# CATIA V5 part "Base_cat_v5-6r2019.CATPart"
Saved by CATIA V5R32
Part number: Base
Bounding box of the stored display mesh (mm): x -32 to 32, y 0 to 144, z 0 to 52
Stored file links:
  D:\PROJECTS\Project 2022\CATIA V5 6R 2022\Resources\Tutorial Files\c16_catia_v5_6r2022_tut\Bench vice\Base_cat_v5-6r2019.CATPart
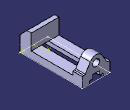
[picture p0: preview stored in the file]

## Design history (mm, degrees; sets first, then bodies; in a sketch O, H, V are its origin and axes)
Body1 (main body)
  Sketch1 on xy-plane, origin (0, 0, 0), H (1, 0, 0), V (0, 1, 0)
    point P1 (-32, 0)
    line L1 (-32, 0) -> (32, 0)
    line L2 (32, 0) -> (32, 144)
    line L3 (32, 144) -> (-32, 144)
    line L4 (-32, 144) -> (-32, 0)
    length L1 = 64
    length L2 = 144
    distance V L2 = 32
    coincidence: P1 H
    horizontal: L1 H, L3 H
    vertical: L2 V, L4 V
  Pad1: profile Sketch1, direction (0, 0, 1), length 16
  Sketch2 on face of Pad1, origin (32, 0, 0), H (0, 1, 0), V (0, 0, 1)
    point P1 (0, 16)
    line L1 (0, 16) -> (0, 36)
    point P2 (0, 36)
    line L2 (26, 52) -> (26, 16)
    line L3 (26, 16) -> (0, 16)
    reference projected line E1 (144, 16) -> (0, 16) from edge of Pad1
    line L4 (26, 52) -> (16, 52)
    point P5 (16, 52)
    line L5 (16, 52) -> (0, 36)
    length L2 = 36
    distance P5 P2 H = 16
    distance P5 P2 V = 16
    length L3 = 26
    coincidence: P1 V, E1 L3
    vertical: L1 V, L2 V
    horizontal: L3 H, L4 H
  Pad2: profile Sketch2, direction (-1, 0, 0), length 64
  Sketch3 on face of Pad1, origin (0, 144, 0), H (-1, 0, 0), V (0, 0, 1)
    line L1 (-32, 16) -> (-32, 24)
    point P2 (32, 24)
    line L2 (32, 24) -> (32, 16)
    line L3 (32, 16) -> (-32, 16)
    reference projected line E1 (32, 16) -> (-32, 16) from edge of Pad1
    line L4 (32, 24) -> (26, 24)
    point P4 (26, 24)
    line L5 (26, 24) -> (13.6777, 44.3018)
    point P5 (0, 52)
    line L6 (-13.6777, 44.3018) -> (-26, 24)
    point P6 (-26, 24)
    line L7 (-26, 24) -> (-32, 24)
    reference projected line E2 (32, 52) -> (-32, 52) from edge of Pad2
    reference projected line E3 (32, 16) -> (32, 52) from edge of Pad2
    reference projected line E4 (-32, 0) -> (-32, 16) from edge of Pad1
    arc A1 centre (0, 36) radius 16 from (13.6777, 44.3018) to (-13.6777, 44.3018) ccw
    point P8 (0, 36)
    reference projected line E5 (32, 52) -> (-32, 52) from edge of Pad2
    circle A2 centre (0, 36) radius 8
    distance H P2 = 24
    distance P6 P4 = 52
    distance P6 V = 26
    radius A1 = 16
    radius A2 = 8
    vertical: L1 V, L2 V
    horizontal: L3 H, L4 H, L7 H
    coincidence: L3 E1, P5 V, P6 L4, P5 E2, L2 E3, L1 E4, P8 V
    tangency: A1 E5, L6 A1, A1 L5
  Pad3: profile Sketch3, direction (0, -1, 0), length 22
  Fillet1: radius 3, on 2 edges
  Sketch4 on face of Pad1, origin (0, 144, 0), H (-1, 0, 0), V (0, 0, 1)
    point P1 (-16, 0)
    line L1 (-16, 0) -> (-16, 7)
    point P2 (-16, 7)
    line L2 (-16, 7) -> (-8, 7)
    point P3 (-8, 7)
    line L3 (-8, 7) -> (-8, 16)
    point P4 (-8, 16)
    line L4 (-8, 16) -> (0, 16)
    point P5 (0, 16)
    point P6 (16, 7)
    point P7 (16, 0)
    line L5 (16, 0) -> (16, 7)
    point P8 (8, 7)
    line L6 (16, 7) -> (8, 7)
    point P9 (8, 16)
    line L7 (8, 7) -> (8, 16)
    point P10 (0, 16)
    line L8 (8, 16) -> (0, 16)
    line L9 (-16, 0) -> (16, 0)
    point P11 (16, 0)
    distance L1 V = 16
    distance L3 V = 8
    distance H L4 = 16
    distance H L2 = 7
    coincidence: P1 H, P5 V, P7 P11, P5 P10
    vertical: L1 V, L3 V
    horizontal: L2 H, L4 H, L9 H
    symmetry: P2 P6 V, P1 P7 V, L1 L5 V, P3 P8 V, L2 L6 V, P4 P9 V, L3 L7 V, P5 P10 V, L4 L8 V
  Pocket1: profile Sketch4, direction (0, -1, 0), through (limit type 3)
  Sketch5 on face of Pad1, origin (0, 0, 0), H (1, 0, 0), V (0, -1, 0)
    circle A1 centre (22, -38) radius 3
    point P1 (22, -38)
    reference projected line E1 (32, 0) -> (-32, 0) from edge of Pad1
    radius A1 = 3
    distance P1 E1 = 38
    distance V P1 = 22
  Pocket2: profile Sketch5, direction (0, 0, 1), length 12
  RectPattern1: of Pocket2, direction 1 instances 2, spacing 70, along edge of Pad1, direction 2 instances 2, spacing 44, along edge of Pad1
